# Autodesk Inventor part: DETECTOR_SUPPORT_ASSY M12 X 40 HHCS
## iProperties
Shininess: 64.0
Length Units: 11272
Angle Units: 11279
Time Units: 11290
Mass Units: 11286
Length Display Precision: 3
Angle Display Precision: 2
Compacted: True
Part Number: DETECTOR_SUPPORT_ASSY M12 X 40 HHCS
Document SubType Name: Modeling
Created: 2004-08
Designer: John Blackburn
Material: MILD_STEEL
Manufacturer: Standard
Standards Organization: Custom
Density: 0.0
Volumn: 0.0
Area: 0.0
PropertySet Name: Model Information
Control State: 0
Master: False
Checked Out: False
Author: John Blackburn
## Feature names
1. Base1
